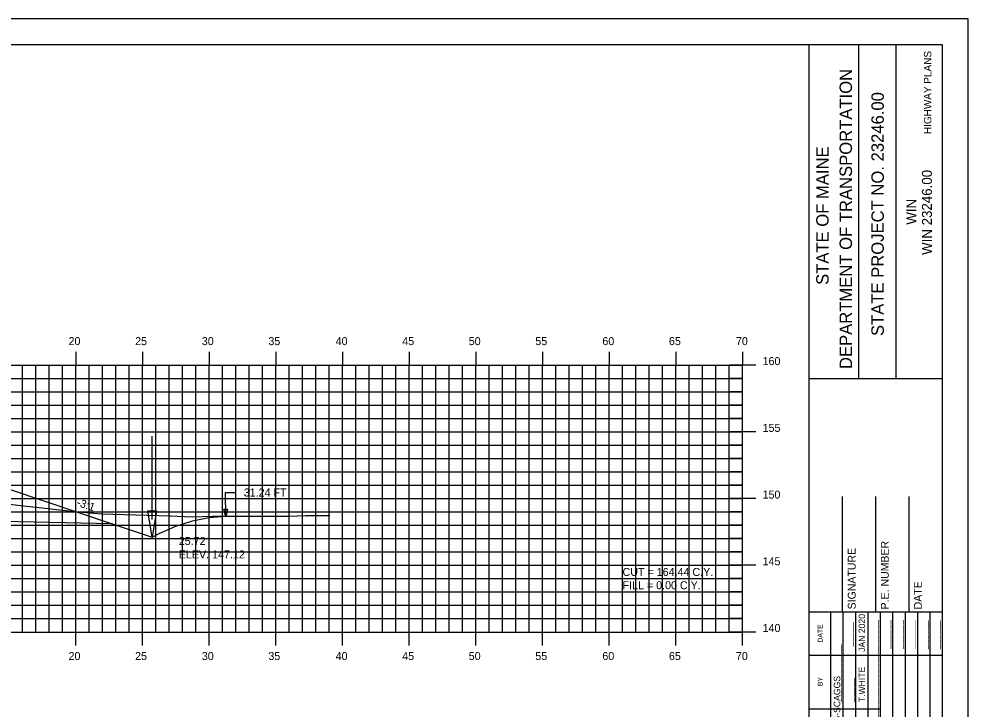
# Model space of a CAD drawing. Extents: x 1147190 to 1147360, y 608981 to 609091.
# Drawn here: x 1147288.7 to 1147359.8, y 609039.6 to 609091.3 of the extents above; entities that cross this region are included whole.
import ezdxf

# ---------------------------------------------------------------- set-up
doc = ezdxf.new("R2010")
doc.units = 0
for name, color, linetype in [('ANNOTATION', 7, 'Continuous'), ('BORDER', 7, 'Continuous'), ('D_Drainage_Ditch_Line', 7, 'Continuous'), ('D_Roadway_SlopeLines', 7, 'Continuous'), ('D_Roadway_SubGrade', 7, 'Continuous'), ('D_Text_Standard', 7, 'Continuous'), ('H_V ANNOTATION', 7, 'Continuous'), ('HIGHWAY_TITLE', 7, 'Continuous'), ('MAJOR', 7, 'Continuous'), ('MINOR', 7, 'Continuous'), ('PLOT BOUNDARY', 7, 'Continuous'), ('S_Roadway_Centerline', 7, 'Continuous')]:
    doc.layers.add(name, color=color, linetype=linetype)

msp = doc.modelspace()

# ---------------------------------------------------------------- linework, layer by layer
at = {"layer": 'BORDER'}
for p, q in [((1147347.941, 608984.335), (1147347.941, 609089.335)), ((1147351.67, 609064.332), (1147351.67, 609089.332)), ((1147354.465, 609064.332), (1147354.465, 609089.332)), ((1147347.942, 609064.329), (1147357.941, 609064.329)), ((1147350.441, 609046.838), (1147350.441, 609055.485)), ((1147352.941, 609046.838), (1147352.941, 609055.485)), ((1147355.441, 609046.838), (1147355.441, 609055.485)), ((1147347.941, 609046.838), (1147357.941, 609046.838))]:
    msp.add_line(p, q, dxfattribs=at)
msp.add_lwpolyline([(1147197.941, 608984.335), (1147357.941, 608984.335), (1147357.941, 609089.335), (1147197.941, 609089.335)], close=True, dxfattribs=at)
for points in [[(1147349.556, 609043.588), (1147349.556, 609046.838)], [(1147350.489, 609029.341), (1147350.489, 609046.838)], [(1147351.42, 609046.838), (1147351.42, 609029.341)], [(1147352.352, 609029.341), (1147352.352, 609046.838)], [(1147353.284, 609029.341), (1147353.284, 609046.838)], [(1147354.215, 609029.341), (1147354.215, 609046.838)], [(1147355.147, 609029.341), (1147355.147, 609046.838)], [(1147356.079, 609029.341), (1147356.079, 609046.838)], [(1147357.01, 609029.341), (1147357.01, 609046.838)], [(1147349.557, 609029.341), (1147349.557, 609046.132)], [(1147347.941, 609043.588), (1147357.941, 609043.588)], [(1147347.941, 609039.588), (1147349.557, 609039.588)], [(1147349.556, 609039.588), (1147353.283, 609039.588)]]:
    msp.add_lwpolyline(points, dxfattribs=at)
at = {"layer": 'D_Drainage_Ditch_Line'}
msp.add_line((1147298.664, 609053.765), (1147298.665, 609060.009), dxfattribs=at)
msp.add_lwpolyline([(1147298.336, 609054.422), (1147298.992, 609054.422), (1147298.664, 609052.453)], close=True, dxfattribs=at)
at = {"layer": 'D_Roadway_SlopeLines'}
for points in [[(1147295.664, 609053.453), (1147298.664, 609052.453)], [(1147298.664, 609052.453), (1147299.184, 609052.713), (1147300.434, 609053.263), (1147301.684, 609053.663), (1147302.934, 609053.912), (1147304.184, 609054.012)]]:
    msp.add_lwpolyline(points, dxfattribs=at)
at = {"layer": 'D_Roadway_SubGrade'}
msp.add_lwpolyline([(1147283.941, 609055.771), (1147283.941, 609055.938), (1147287.941, 609055.778), (1147287.941, 609056.028), (1147287.941, 609056.028), (1147295.664, 609053.453), (1147283.941, 609053.688)], close=True, dxfattribs=at)
at = {"layer": 'D_Text_Standard'}
msp.add_lwpolyline([(1147304.184, 609053.963), (1147304.174, 609055.79), (1147304.854, 609055.79)], dxfattribs=at)
msp.add_lwpolyline([(1147304.184, 609053.963), (1147304.035, 609054.544), (1147304.326, 609054.546)], close=True, dxfattribs=at)
at = {"layer": 'MAJOR'}
for p, q in [((1147292.941, 609066.337), (1147292.941, 609065.335)), ((1147297.941, 609066.337), (1147297.941, 609065.335)), ((1147302.941, 609066.337), (1147302.941, 609065.335)), ((1147307.941, 609066.337), (1147307.941, 609065.335)), ((1147312.941, 609066.337), (1147312.941, 609065.335)), ((1147317.941, 609066.337), (1147317.941, 609065.335)), ((1147322.941, 609066.337), (1147322.941, 609065.335)), ((1147327.941, 609066.337), (1147327.941, 609065.335)), ((1147332.941, 609066.337), (1147332.941, 609065.335)), ((1147337.941, 609066.337), (1147337.941, 609065.335)), ((1147342.941, 609066.337), (1147342.941, 609065.335)), ((1147202.941, 609065.335), (1147342.941, 609065.335)), ((1147202.941, 609065.335), (1147342.941, 609065.335)), ((1147292.941, 609045.335), (1147292.941, 609065.335)), ((1147297.941, 609045.335), (1147297.941, 609065.335)), ((1147302.941, 609045.335), (1147302.941, 609065.335)), ((1147307.941, 609045.335), (1147307.941, 609065.335)), ((1147312.941, 609045.335), (1147312.941, 609065.335)), ((1147317.941, 609045.335), (1147317.941, 609065.335)), ((1147322.941, 609045.335), (1147322.941, 609065.335)), ((1147327.941, 609045.335), (1147327.941, 609065.335)), ((1147332.941, 609045.335), (1147332.941, 609065.335)), ((1147337.941, 609045.335), (1147337.941, 609065.335)), ((1147343.943, 609065.335), (1147341.939, 609065.335)), ((1147342.941, 609045.335), (1147342.941, 609065.335)), ((1147342.941, 609045.335), (1147342.941, 609065.335)), ((1147202.941, 609060.335), (1147342.941, 609060.335)), ((1147343.943, 609060.335), (1147341.939, 609060.335)), ((1147202.941, 609055.335), (1147342.941, 609055.335)), ((1147343.943, 609055.335), (1147341.939, 609055.335)), ((1147202.941, 609050.335), (1147342.941, 609050.335)), ((1147343.943, 609050.335), (1147341.939, 609050.335)), ((1147202.941, 609045.335), (1147342.941, 609045.335)), ((1147202.941, 609045.335), (1147342.941, 609045.335)), ((1147292.941, 609044.333), (1147292.941, 609045.335)), ((1147297.941, 609044.333), (1147297.941, 609045.335)), ((1147302.941, 609044.333), (1147302.941, 609045.335)), ((1147307.941, 609044.333), (1147307.941, 609045.335)), ((1147312.941, 609044.333), (1147312.941, 609045.335)), ((1147317.941, 609044.333), (1147317.941, 609045.335)), ((1147322.941, 609044.333), (1147322.941, 609045.335)), ((1147327.941, 609044.333), (1147327.941, 609045.335)), ((1147332.941, 609044.333), (1147332.941, 609045.335)), ((1147337.941, 609044.333), (1147337.941, 609045.335)), ((1147343.943, 609045.335), (1147341.939, 609045.335)), ((1147342.941, 609044.333), (1147342.941, 609045.335))]:
    msp.add_line(p, q, dxfattribs=at)
at = {"layer": 'MINOR'}
for p, q in [((1147288.941, 609045.335), (1147288.941, 609065.335)), ((1147289.941, 609045.335), (1147289.941, 609065.335)), ((1147290.941, 609045.335), (1147290.941, 609065.335)), ((1147291.941, 609045.335), (1147291.941, 609065.335)), ((1147293.941, 609045.335), (1147293.941, 609065.335)), ((1147294.941, 609045.335), (1147294.941, 609065.335)), ((1147295.941, 609045.335), (1147295.941, 609065.335)), ((1147296.941, 609045.335), (1147296.941, 609065.335)), ((1147298.941, 609045.335), (1147298.941, 609065.335)), ((1147299.941, 609045.335), (1147299.941, 609065.335)), ((1147300.941, 609045.335), (1147300.941, 609065.335)), ((1147301.941, 609045.335), (1147301.941, 609065.335)), ((1147303.941, 609045.335), (1147303.941, 609065.335)), ((1147304.941, 609045.335), (1147304.941, 609065.335)), ((1147305.941, 609045.335), (1147305.941, 609065.335)), ((1147306.941, 609045.335), (1147306.941, 609065.335)), ((1147308.941, 609045.335), (1147308.941, 609065.335)), ((1147309.941, 609045.335), (1147309.941, 609065.335)), ((1147310.941, 609045.335), (1147310.941, 609065.335)), ((1147311.941, 609045.335), (1147311.941, 609065.335)), ((1147313.941, 609045.335), (1147313.941, 609065.335)), ((1147314.941, 609045.335), (1147314.941, 609065.335)), ((1147315.941, 609045.335), (1147315.941, 609065.335)), ((1147316.941, 609045.335), (1147316.941, 609065.335)), ((1147318.941, 609045.335), (1147318.941, 609065.335)), ((1147319.941, 609045.335), (1147319.941, 609065.335)), ((1147320.941, 609045.335), (1147320.941, 609065.335)), ((1147321.941, 609045.335), (1147321.941, 609065.335)), ((1147323.941, 609045.335), (1147323.941, 609065.335)), ((1147324.941, 609045.335), (1147324.941, 609065.335)), ((1147325.941, 609045.335), (1147325.941, 609065.335)), ((1147326.941, 609045.335), (1147326.941, 609065.335)), ((1147328.941, 609045.335), (1147328.941, 609065.335)), ((1147329.941, 609045.335), (1147329.941, 609065.335)), ((1147330.941, 609045.335), (1147330.941, 609065.335)), ((1147331.941, 609045.335), (1147331.941, 609065.335)), ((1147333.941, 609045.335), (1147333.941, 609065.335)), ((1147334.941, 609045.335), (1147334.941, 609065.335)), ((1147335.941, 609045.335), (1147335.941, 609065.335)), ((1147336.941, 609045.335), (1147336.941, 609065.335)), ((1147338.941, 609045.335), (1147338.941, 609065.335)), ((1147339.941, 609045.335), (1147339.941, 609065.335)), ((1147340.941, 609045.335), (1147340.941, 609065.335)), ((1147341.941, 609045.335), (1147341.941, 609065.335)), ((1147202.941, 609064.335), (1147342.941, 609064.335)), ((1147342.941, 609064.335), (1147341.939, 609064.335)), ((1147202.941, 609063.335), (1147342.941, 609063.335)), ((1147342.941, 609063.335), (1147341.939, 609063.335)), ((1147202.941, 609062.335), (1147342.941, 609062.335)), ((1147342.941, 609062.335), (1147341.939, 609062.335)), ((1147202.941, 609061.335), (1147342.941, 609061.335)), ((1147342.941, 609061.335), (1147341.939, 609061.335)), ((1147202.941, 609059.335), (1147342.941, 609059.335)), ((1147342.941, 609059.335), (1147341.939, 609059.335)), ((1147202.941, 609058.335), (1147342.941, 609058.335)), ((1147342.941, 609058.335), (1147341.939, 609058.335)), ((1147202.941, 609057.335), (1147342.941, 609057.335)), ((1147342.941, 609057.335), (1147341.939, 609057.335)), ((1147202.941, 609056.335), (1147342.941, 609056.335)), ((1147342.941, 609056.335), (1147341.939, 609056.335)), ((1147202.941, 609054.335), (1147342.941, 609054.335)), ((1147342.941, 609054.335), (1147341.939, 609054.335)), ((1147202.941, 609053.335), (1147342.941, 609053.335)), ((1147342.941, 609053.335), (1147341.939, 609053.335)), ((1147202.941, 609052.335), (1147342.941, 609052.335)), ((1147342.941, 609052.335), (1147341.939, 609052.335)), ((1147202.941, 609051.335), (1147342.941, 609051.335)), ((1147342.941, 609051.335), (1147341.939, 609051.335)), ((1147202.941, 609049.335), (1147342.941, 609049.335)), ((1147342.941, 609049.335), (1147341.939, 609049.335)), ((1147202.941, 609048.335), (1147342.941, 609048.335)), ((1147342.941, 609048.335), (1147341.939, 609048.335)), ((1147202.941, 609047.335), (1147342.941, 609047.335)), ((1147342.941, 609047.335), (1147341.939, 609047.335)), ((1147202.941, 609046.335), (1147342.941, 609046.335)), ((1147342.941, 609046.335), (1147341.939, 609046.335))]:
    msp.add_line(p, q, dxfattribs=at)
at = {"layer": 'PLOT BOUNDARY'}
msp.add_lwpolyline([(1147189.848, 608981.276), (1147359.848, 608981.276), (1147359.848, 609091.276), (1147189.848, 609091.276)], close=True, dxfattribs=at)
at = {"layer": 'S_Roadway_Centerline'}
msp.add_lwpolyline([(1147218.688, 609053.977), (1147226.482, 609054.305), (1147226.795, 609054.318), (1147244.605, 609054.889), (1147253.434, 609054.334), (1147254.688, 609054.274), (1147257.845, 609055.05), (1147258.383, 609055.178), (1147258.823, 609055.179), (1147261.29, 609055.101), (1147268.386, 609055.21), (1147272.587, 609055.279), (1147275.438, 609055.212), (1147283.483, 609055.129), (1147286.037, 609055.041), (1147287.273, 609054.996), (1147292.854, 609054.376), (1147294.865, 609054.203), (1147300.019, 609054.043), (1147301.689, 609053.963), (1147303.16, 609054.01), (1147308.976, 609054.019), (1147310.153, 609054.07), (1147311.998, 609054.066)], dxfattribs=at)

# ---------------------------------------------------------------- texts
at = {"layer": 'ANNOTATION'}
msp.add_text('-3:1', height=0.6, rotation=341.56521, dxfattribs=at).set_placement((1147292.952, 609054.811))
at = {"layer": 'BORDER'}
for s, height, p in [('DEPARTMENT OF TRANSPORTATION', 0.93176, (1147351.148, 609065.041)), ('STATE PROJECT NO. 23246.00', 0.93176, (1147353.533, 609067.517)), ('STATE OF MAINE', 0.93176, (1147349.396, 609071.347)), ('WIN 23246.00', 0.74527, (1147357.137, 609073.596)), ('WIN', 0.7453, (1147355.978, 609075.865)), ('P.E. NUMBER', 0.59055, (1147353.902, 609047.03)), ('SIGNATURE', 0.5906, (1147351.422, 609047.03)), ('DATE', 0.5906, (1147356.382, 609047.03)), ('JAN 2020', 0.4845, (1147352.127, 609043.843)), ('DATE', 0.3714, (1147348.945, 609044.544)), ('_____', 0.4845, (1147351.158, 609044.243)), ('______', 0.4845, (1147353.022, 609044.063)), ('______', 0.4845, (1147353.953, 609044.065)), ('______', 0.4845, (1147354.885, 609044.067)), ('______', 0.4845, (1147355.817, 609044.067)), ('______', 0.4845, (1147356.749, 609044.036)), ('______', 0.4845, (1147357.68, 609044.036)), ('____________', 0.48455, (1147350.264, 609040.073)), ('____________', 0.48455, (1147353.022, 609040.073)), ('T.WHITE', 0.4845, (1147352.127, 609040.073)), ('M YOUNG-SCAGGS', 0.48455, (1147350.264, 609035.961)), ('BY', 0.3714, (1147348.945, 609041.273)), ('_____', 0.4845, (1147351.196, 609040.073)), ('____________', 0.48455, (1147353.022, 609035.961))]:
    msp.add_text(s, height=height, rotation=90, dxfattribs=at).set_placement(p)
at = {"layer": 'D_Text_Standard'}
for s, p in [('31.24 FT', (1147305.534, 609055.49)), ('25.72', (1147300.664, 609051.853)), ('ELEV. 147.12', (1147300.664, 609050.851)), ('CUT = 164.44 C.Y.', (1147333.941, 609049.535)), ('FILL = 0.00 C.Y.', (1147333.941, 609048.539))]:
    msp.add_text(s, height=0.6, dxfattribs=at).set_placement(p)
at = {"layer": 'H_V ANNOTATION'}
for s, p in [('20', (1147292.395, 609066.835)), ('25', (1147297.387, 609066.835)), ('30', (1147302.39, 609066.835)), ('35', (1147307.382, 609066.835)), ('40', (1147312.427, 609066.835)), ('45', (1147317.419, 609066.835)), ('50', (1147322.406, 609066.835)), ('55', (1147327.398, 609066.835)), ('60', (1147332.427, 609066.835)), ('65', (1147337.419, 609066.835)), ('70', (1147342.443, 609066.835)), ('160', (1147344.441, 609065.335)), ('155', (1147344.441, 609060.335)), ('150', (1147344.441, 609055.335)), ('145', (1147344.441, 609050.335)), ('140', (1147344.441, 609045.335)), ('20', (1147292.395, 609043.235)), ('25', (1147297.387, 609043.235)), ('30', (1147302.39, 609043.235)), ('35', (1147307.382, 609043.235)), ('40', (1147312.427, 609043.235)), ('45', (1147317.419, 609043.235)), ('50', (1147322.406, 609043.235)), ('55', (1147327.398, 609043.235)), ('60', (1147332.427, 609043.235)), ('65', (1147337.419, 609043.235)), ('70', (1147342.443, 609043.235))]:
    msp.add_text(s, height=0.6, dxfattribs=at).set_placement(p)
at = {"layer": 'HIGHWAY_TITLE'}
msp.add_text('HIGHWAY PLANS', height=0.55901, rotation=90, dxfattribs=at).set_placement((1147357.099, 609082.65))

doc.saveas('drawing.dxf')
